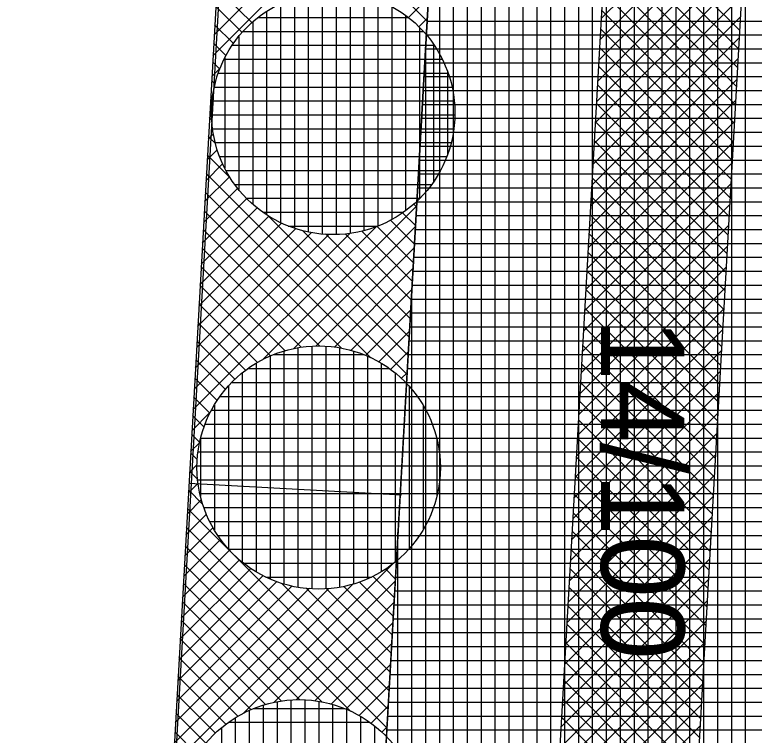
# Model space of a CAD drawing. Extents: x -565346 to -564154, y -1097386 to -1095620.
# Drawn here: x -564304.7 to -564294.07, y -1097238.87 to -1097228.5 of the extents above; entities that cross this region are included whole.
import ezdxf

# ---------------------------------------------------------------- set-up
doc = ezdxf.new("R2010")
doc.units = 0
for name, color, linetype in [('Vrstva 1', 7, 'Continuous'), ('Vrstva 40', 7, 'Continuous'), ('Vrstva 41', 7, 'Continuous'), ('Vrstva 42', 7, 'Continuous'), ('Vrstva 43', 7, 'Continuous'), ('Vrstva 44', 7, 'Continuous')]:
    doc.layers.add(name, color=color, linetype=linetype)

msp = doc.modelspace()

# ---------------------------------------------------------------- linework, layer by layer
at = {"layer": 'Vrstva 1'}
msp.add_line((-564307.09, -1097322.09), (-564296.5, -1097135.53), dxfattribs=at)
at = {"layer": 'Vrstva 41'}
msp.add_line((-564299.138, -1097235.414), (-564302.199, -1097235.242), dxfattribs=at)
msp.add_lwpolyline([(-564307.383, -1097332.191), (-564304.399, -1097332.838), (-564304.096, -1097322.37), (-564303.226, -1097307.04), (-564296.016, -1097180.02), (-564294.347, -1097150.646), (-564297.42, -1097150.37), (-564307.09, -1097322.09)], close=True, dxfattribs=at)
at = {"layer": 'Vrstva 42'}
for p, q in [((-564301.662, -1097225.698), (-564298.773, -1097228.587)), ((-564298.618, -1097225.855), (-564301.853, -1097229.09)), ((-564299.264, -1097226.218), (-564301.836, -1097228.79)), ((-564294.143, -1097226.43), (-564296.267, -1097228.554)), ((-564294.16, -1097226.73), (-564296.284, -1097228.854)), ((-564296.169, -1097226.831), (-564294.273, -1097228.727)), ((-564294.177, -1097227.03), (-564296.301, -1097229.154)), ((-564296.184, -1097227.099), (-564294.288, -1097228.995)), ((-564294.194, -1097227.33), (-564296.318, -1097229.454)), ((-564296.199, -1097227.367), (-564294.304, -1097229.263)), ((-564294.211, -1097227.63), (-564296.335, -1097229.754)), ((-564296.215, -1097227.634), (-564294.319, -1097229.53)), ((-564296.23, -1097227.902), (-564294.334, -1097229.798)), ((-564294.228, -1097227.93), (-564296.352, -1097230.054)), ((-564301.798, -1097228.107), (-564301.293, -1097228.612)), ((-564294.245, -1097228.23), (-564296.369, -1097230.354)), ((-564296.245, -1097228.17), (-564294.349, -1097230.065)), ((-564298.754, -1097228.254), (-564299.042, -1097228.542)), ((-564301.813, -1097228.375), (-564301.433, -1097228.754)), ((-564296.26, -1097228.437), (-564294.364, -1097230.333)), ((-564298.771, -1097228.554), (-564298.892, -1097228.675)), ((-564294.262, -1097228.529), (-564296.386, -1097230.653)), ((-564301.828, -1097228.643), (-564301.558, -1097228.913)), ((-564296.275, -1097228.705), (-564294.38, -1097230.601)), ((-564294.279, -1097228.829), (-564296.403, -1097230.953)), ((-564301.843, -1097228.911), (-564301.665, -1097229.088)), ((-564296.291, -1097228.973), (-564294.395, -1097230.868)), ((-564301.858, -1097229.179), (-564301.754, -1097229.283)), ((-564294.296, -1097229.129), (-564296.42, -1097231.253)), ((-564301.748, -1097229.268), (-564301.87, -1097229.39)), ((-564296.306, -1097229.24), (-564294.41, -1097231.136)), ((-564301.873, -1097229.446), (-564301.822, -1097229.498)), ((-564294.313, -1097229.429), (-564296.437, -1097231.553)), ((-564296.321, -1097229.508), (-564294.425, -1097231.404)), ((-564301.888, -1097229.714), (-564301.864, -1097229.738)), ((-564301.852, -1097229.655), (-564301.887, -1097229.69)), ((-564294.33, -1097229.729), (-564296.454, -1097231.853)), ((-564296.336, -1097229.776), (-564294.44, -1097231.671)), ((-564301.872, -1097229.957), (-564301.904, -1097229.989)), ((-564301.903, -1097229.982), (-564301.868, -1097230.017)), ((-564294.347, -1097230.029), (-564296.471, -1097232.153)), ((-564296.351, -1097230.043), (-564294.456, -1097231.939)), ((-564301.846, -1097230.214), (-564301.92, -1097230.289)), ((-564301.918, -1097230.25), (-564301.816, -1097230.352)), ((-564294.364, -1097230.329), (-564296.488, -1097232.453)), ((-564296.367, -1097230.311), (-564294.471, -1097232.207)), ((-564301.791, -1097230.443), (-564301.937, -1097230.589)), ((-564301.933, -1097230.517), (-564301.6, -1097230.851)), ((-564296.382, -1097230.578), (-564294.486, -1097232.474)), ((-564301.712, -1097230.647), (-564301.954, -1097230.888)), ((-564294.381, -1097230.628), (-564296.505, -1097232.753)), ((-564301.948, -1097230.785), (-564299.061, -1097233.672)), ((-564301.613, -1097230.83), (-564301.971, -1097231.188)), ((-564296.397, -1097230.846), (-564294.501, -1097232.742)), ((-564301.496, -1097230.996), (-564301.988, -1097231.488)), ((-564294.398, -1097230.928), (-564296.522, -1097233.052)), ((-564301.963, -1097231.053), (-564299.58, -1097233.436)), ((-564301.363, -1097231.146), (-564302.005, -1097231.788)), ((-564296.412, -1097231.114), (-564294.516, -1097233.01)), ((-564301.214, -1097231.28), (-564302.022, -1097232.087)), ((-564301.979, -1097231.321), (-564300.002, -1097233.297)), ((-564298.924, -1097231.252), (-564301.129, -1097233.457)), ((-564298.964, -1097231.223), (-564298.925, -1097231.263)), ((-564294.415, -1097231.228), (-564296.539, -1097233.352)), ((-564301.049, -1097231.398), (-564302.039, -1097232.387)), ((-564301.061, -1097231.39), (-564299.046, -1097233.404)), ((-564299.123, -1097231.348), (-564298.94, -1097231.531)), ((-564296.427, -1097231.381), (-564294.531, -1097233.277)), ((-564300.866, -1097231.498), (-564302.055, -1097232.687)), ((-564299.298, -1097231.455), (-564298.955, -1097231.798)), ((-564294.432, -1097231.528), (-564296.556, -1097233.652)), ((-564299.501, -1097231.547), (-564302.14, -1097234.185)), ((-564299.882, -1097231.645), (-564302.123, -1097233.886)), ((-564300.435, -1097231.632), (-564302.089, -1097233.286)), ((-564300.664, -1097231.578), (-564302.072, -1097232.987)), ((-564301.994, -1097231.588), (-564300.317, -1097233.265)), ((-564298.941, -1097231.552), (-564300.689, -1097233.301)), ((-564300.562, -1097231.606), (-564299.031, -1097233.137)), ((-564299.708, -1097231.612), (-564298.985, -1097232.334)), ((-564299.493, -1097231.544), (-564298.97, -1097232.066)), ((-564300.178, -1097231.658), (-564302.106, -1097233.586)), ((-564300.232, -1097231.653), (-564299.016, -1097232.869)), ((-564299.948, -1097231.654), (-564299.001, -1097232.601)), ((-564296.443, -1097231.649), (-564294.547, -1097233.545)), ((-564302.009, -1097231.856), (-564300.581, -1097233.284)), ((-564298.958, -1097231.852), (-564300.372, -1097233.266)), ((-564294.449, -1097231.828), (-564296.573, -1097233.952)), ((-564296.458, -1097231.917), (-564294.562, -1097233.813)), ((-564302.024, -1097232.124), (-564300.814, -1097233.334)), ((-564298.975, -1097232.152), (-564300.104, -1097233.281)), ((-564294.466, -1097232.128), (-564296.59, -1097234.252)), ((-564296.473, -1097232.184), (-564294.577, -1097234.08)), ((-564302.039, -1097232.392), (-564301.024, -1097233.407)), ((-564298.992, -1097232.452), (-564299.869, -1097233.329)), ((-564294.483, -1097232.428), (-564296.607, -1097234.552)), ((-564296.488, -1097232.452), (-564294.592, -1097234.348)), ((-564302.054, -1097232.659), (-564301.213, -1097233.501)), ((-564299.009, -1097232.752), (-564299.659, -1097233.401)), ((-564294.5, -1097232.728), (-564296.624, -1097234.852)), ((-564296.503, -1097232.72), (-564294.607, -1097234.616)), ((-564302.069, -1097232.927), (-564301.382, -1097233.614)), ((-564294.517, -1097233.027), (-564296.641, -1097235.151)), ((-564296.519, -1097232.987), (-564294.623, -1097234.883)), ((-564299.026, -1097233.052), (-564299.468, -1097233.493)), ((-564302.084, -1097233.195), (-564301.535, -1097233.744)), ((-564294.534, -1097233.327), (-564296.658, -1097235.451)), ((-564296.534, -1097233.255), (-564294.638, -1097235.151)), ((-564299.043, -1097233.352), (-564299.297, -1097233.605)), ((-564302.099, -1097233.463), (-564301.672, -1097233.89)), ((-564296.549, -1097233.523), (-564294.653, -1097235.419)), ((-564299.06, -1097233.651), (-564299.143, -1097233.734)), ((-564294.551, -1097233.627), (-564296.675, -1097235.751)), ((-564302.114, -1097233.731), (-564301.793, -1097234.052)), ((-564296.564, -1097233.79), (-564294.668, -1097235.686)), ((-564294.568, -1097233.927), (-564296.692, -1097236.051)), ((-564302.129, -1097233.998), (-564301.897, -1097234.231)), ((-564296.579, -1097234.058), (-564294.683, -1097235.954)), ((-564301.891, -1097234.219), (-564302.157, -1097234.485)), ((-564302.144, -1097234.266), (-564301.981, -1097234.429)), ((-564294.585, -1097234.227), (-564296.709, -1097236.351)), ((-564296.594, -1097234.326), (-564294.699, -1097236.221)), ((-564302.159, -1097234.534), (-564302.045, -1097234.648)), ((-564294.602, -1097234.527), (-564296.726, -1097236.651)), ((-564296.61, -1097234.593), (-564294.714, -1097236.489)), ((-564302.047, -1097234.659), (-564302.174, -1097234.785)), ((-564302.175, -1097234.802), (-564302.078, -1097234.898)), ((-564294.619, -1097234.827), (-564296.743, -1097236.951)), ((-564296.625, -1097234.861), (-564294.729, -1097236.757)), ((-564302.082, -1097234.976), (-564302.19, -1097235.085)), ((-564302.19, -1097235.069), (-564302.075, -1097235.184)), ((-564294.636, -1097235.126), (-564296.76, -1097237.25)), ((-564296.64, -1097235.129), (-564294.744, -1097237.024)), ((-564302.067, -1097235.244), (-564302.207, -1097235.384)), ((-564302.205, -1097235.337), (-564302.002, -1097235.54)), ((-564294.653, -1097235.426), (-564296.778, -1097237.55)), ((-564296.655, -1097235.396), (-564294.759, -1097237.292)), ((-564302.019, -1097235.479), (-564302.224, -1097235.684)), ((-564302.22, -1097235.605), (-564299.335, -1097238.49)), ((-564296.67, -1097235.664), (-564294.775, -1097237.56)), ((-564301.947, -1097235.689), (-564302.241, -1097235.984)), ((-564294.67, -1097235.726), (-564296.795, -1097237.85)), ((-564301.855, -1097235.88), (-564302.258, -1097236.283)), ((-564302.235, -1097235.873), (-564299.35, -1097238.757)), ((-564296.686, -1097235.931), (-564294.79, -1097237.827)), ((-564301.743, -1097236.051), (-564302.275, -1097236.583)), ((-564294.688, -1097236.026), (-564296.812, -1097238.15)), ((-564301.614, -1097236.205), (-564302.292, -1097236.883)), ((-564302.25, -1097236.14), (-564299.868, -1097238.522)), ((-564296.701, -1097236.199), (-564294.805, -1097238.095)), ((-564301.469, -1097236.343), (-564302.309, -1097237.183)), ((-564302.265, -1097236.408), (-564300.287, -1097238.386)), ((-564299.241, -1097236.378), (-564301.412, -1097238.549)), ((-564294.705, -1097236.326), (-564296.829, -1097238.45)), ((-564301.309, -1097236.465), (-564302.326, -1097237.482)), ((-564299.372, -1097236.473), (-564299.229, -1097236.616)), ((-564296.716, -1097236.467), (-564294.82, -1097238.363)), ((-564301.13, -1097236.57), (-564302.342, -1097237.782)), ((-564299.551, -1097236.577), (-564299.244, -1097236.884)), ((-564294.722, -1097236.626), (-564296.846, -1097238.75)), ((-564299.836, -1097236.69), (-564302.427, -1097239.281)), ((-564300.716, -1097236.721), (-564302.376, -1097238.382)), ((-564300.933, -1097236.656), (-564302.359, -1097238.082)), ((-564302.28, -1097236.676), (-564300.601, -1097238.355)), ((-564299.23, -1097236.65), (-564300.971, -1097238.391)), ((-564300.86, -1097236.682), (-564299.32, -1097238.222)), ((-564300.514, -1097236.745), (-564299.305, -1097237.954)), ((-564299.968, -1097236.725), (-564299.274, -1097237.419)), ((-564299.749, -1097236.661), (-564299.259, -1097237.151)), ((-564296.731, -1097236.734), (-564294.835, -1097238.63)), ((-564300.185, -1097236.756), (-564302.41, -1097238.981)), ((-564300.462, -1097236.751), (-564302.393, -1097238.681)), ((-564300.218, -1097236.758), (-564299.289, -1097237.687)), ((-564302.295, -1097236.944), (-564300.864, -1097238.374)), ((-564299.247, -1097236.95), (-564300.654, -1097238.356)), ((-564294.739, -1097236.926), (-564296.863, -1097239.05)), ((-564296.746, -1097237.002), (-564294.851, -1097238.898)), ((-564302.31, -1097237.211), (-564301.097, -1097238.424)), ((-564299.265, -1097237.25), (-564300.386, -1097238.371)), ((-564294.756, -1097237.225), (-564296.88, -1097239.35)), ((-564296.762, -1097237.27), (-564294.866, -1097239.166)), ((-564302.325, -1097237.479), (-564301.307, -1097238.498)), ((-564299.282, -1097237.55), (-564300.151, -1097238.419)), ((-564294.773, -1097237.525), (-564296.897, -1097239.649)), ((-564296.777, -1097237.537), (-564294.881, -1097239.433)), ((-564302.34, -1097237.747), (-564301.495, -1097238.592)), ((-564296.792, -1097237.805), (-564294.896, -1097239.701)), ((-564299.299, -1097237.849), (-564299.94, -1097238.491)), ((-564294.79, -1097237.825), (-564296.914, -1097239.949)), ((-564302.356, -1097238.015), (-564301.665, -1097238.706)), ((-564294.807, -1097238.125), (-564296.931, -1097240.249)), ((-564296.807, -1097238.073), (-564294.911, -1097239.969)), ((-564299.316, -1097238.149), (-564299.749, -1097238.583)), ((-564302.371, -1097238.282), (-564301.817, -1097238.836)), ((-564296.822, -1097238.34), (-564294.926, -1097240.236)), ((-564299.333, -1097238.449), (-564299.578, -1097238.694)), ((-564294.824, -1097238.425), (-564296.948, -1097240.549)), ((-564302.386, -1097238.55), (-564301.954, -1097238.982)), ((-564296.838, -1097238.608), (-564294.942, -1097240.504)), ((-564299.35, -1097238.749), (-564299.424, -1097238.823)), ((-564294.841, -1097238.725), (-564296.965, -1097240.849)), ((-564302.401, -1097238.818), (-564302.075, -1097239.144))]:
    msp.add_line(p, q, dxfattribs=at)
msp.add_lwpolyline([(-564300.922, -1097310.531), (-564298.925, -1097310.644), (-564291.523, -1097180.275), (-564289.854, -1097150.901), (-564291.851, -1097150.788), (-564293.52, -1097180.162), (-564300.73, -1097307.182)], close=True, dxfattribs=at)
at = {"layer": 'Vrstva 43'}
for p, q in [((-564294.19, -1097271.373), (-564294.19, -1097138.944)), ((-564294.39, -1097274.897), (-564294.39, -1097151.403)), ((-564294.59, -1097278.421), (-564294.59, -1097154.926)), ((-564294.79, -1097281.945), (-564294.79, -1097158.449)), ((-564294.99, -1097285.469), (-564294.99, -1097161.972)), ((-564295.19, -1097288.993), (-564295.19, -1097165.495)), ((-564295.39, -1097292.517), (-564295.39, -1097169.017)), ((-564295.59, -1097296.041), (-564295.59, -1097172.54)), ((-564295.79, -1097299.565), (-564295.79, -1097176.063)), ((-564295.99, -1097303.088), (-564295.99, -1097179.586)), ((-564296.19, -1097306.612), (-564296.19, -1097183.108)), ((-564296.39, -1097310.136), (-564296.39, -1097186.631)), ((-564296.59, -1097313.66), (-564296.59, -1097190.154)), ((-564296.79, -1097317.184), (-564296.79, -1097193.677)), ((-564296.99, -1097320.708), (-564296.99, -1097197.2)), ((-564297.19, -1097322.532), (-564297.19, -1097200.722)), ((-564297.39, -1097322.908), (-564297.39, -1097204.245)), ((-564297.59, -1097323.285), (-564297.59, -1097207.768)), ((-564297.79, -1097323.661), (-564297.79, -1097211.291)), ((-564297.99, -1097324.037), (-564297.99, -1097214.814)), ((-564298.19, -1097324.413), (-564298.19, -1097218.336)), ((-564298.39, -1097324.789), (-564298.39, -1097221.859)), ((-564298.59, -1097325.166), (-564298.59, -1097225.382)), ((-564298.772, -1097228.59), (-564291.762, -1097228.59)), ((-564298.783, -1097228.79), (-564291.773, -1097228.79)), ((-564298.79, -1097325.542), (-564298.79, -1097228.905)), ((-564298.795, -1097228.99), (-564291.784, -1097228.99)), ((-564298.806, -1097229.19), (-564291.796, -1097229.19)), ((-564298.818, -1097229.39), (-564291.807, -1097229.39)), ((-564298.829, -1097229.59), (-564291.818, -1097229.59)), ((-564298.84, -1097229.79), (-564291.83, -1097229.79)), ((-564298.852, -1097229.99), (-564291.841, -1097229.99)), ((-564298.863, -1097230.19), (-564291.852, -1097230.19)), ((-564298.874, -1097230.39), (-564291.864, -1097230.39)), ((-564298.886, -1097230.59), (-564291.875, -1097230.59)), ((-564298.897, -1097230.79), (-564291.886, -1097230.79)), ((-564298.908, -1097230.99), (-564291.898, -1097230.99)), ((-564298.92, -1097231.19), (-564291.909, -1097231.19)), ((-564298.931, -1097231.39), (-564291.921, -1097231.39)), ((-564298.942, -1097231.59), (-564291.932, -1097231.59)), ((-564298.954, -1097231.79), (-564291.943, -1097231.79)), ((-564298.965, -1097231.99), (-564291.955, -1097231.99)), ((-564298.977, -1097232.19), (-564291.966, -1097232.19)), ((-564298.99, -1097325.918), (-564298.99, -1097232.427)), ((-564298.988, -1097232.39), (-564291.977, -1097232.39)), ((-564298.999, -1097232.59), (-564291.989, -1097232.59)), ((-564299.011, -1097232.79), (-564292, -1097232.79)), ((-564299.022, -1097232.99), (-564292.011, -1097232.99)), ((-564299.033, -1097233.19), (-564292.023, -1097233.19)), ((-564299.045, -1097233.39), (-564292.034, -1097233.39)), ((-564299.056, -1097233.59), (-564292.045, -1097233.59)), ((-564299.067, -1097233.79), (-564292.057, -1097233.79)), ((-564299.079, -1097233.99), (-564292.068, -1097233.99)), ((-564299.09, -1097234.19), (-564292.079, -1097234.19)), ((-564299.101, -1097234.39), (-564292.091, -1097234.39)), ((-564299.113, -1097234.59), (-564292.102, -1097234.59)), ((-564299.124, -1097234.79), (-564292.114, -1097234.79)), ((-564299.135, -1097234.99), (-564292.125, -1097234.99)), ((-564299.147, -1097235.19), (-564292.136, -1097235.19)), ((-564299.158, -1097235.39), (-564292.148, -1097235.39)), ((-564299.17, -1097235.59), (-564292.159, -1097235.59)), ((-564299.181, -1097235.79), (-564292.17, -1097235.79)), ((-564299.192, -1097235.99), (-564292.182, -1097235.99)), ((-564299.19, -1097326.294), (-564299.19, -1097235.95)), ((-564299.204, -1097236.19), (-564292.193, -1097236.19)), ((-564299.215, -1097236.39), (-564292.204, -1097236.39)), ((-564299.226, -1097236.59), (-564292.216, -1097236.59)), ((-564299.238, -1097236.79), (-564292.227, -1097236.79)), ((-564299.249, -1097236.99), (-564292.238, -1097236.99)), ((-564299.26, -1097237.19), (-564292.25, -1097237.19)), ((-564299.272, -1097237.39), (-564292.261, -1097237.39)), ((-564299.283, -1097237.59), (-564292.272, -1097237.59)), ((-564299.294, -1097237.79), (-564292.284, -1097237.79)), ((-564299.306, -1097237.99), (-564292.295, -1097237.99)), ((-564299.317, -1097238.19), (-564292.307, -1097238.19)), ((-564299.329, -1097238.39), (-564292.318, -1097238.39)), ((-564299.34, -1097238.59), (-564292.329, -1097238.59)), ((-564299.351, -1097238.79), (-564292.341, -1097238.79))]:
    msp.add_line(p, q, dxfattribs=at)
msp.add_lwpolyline([(-564283.37, -1096906.18), (-564284.87, -1096930.83), (-564282.373, -1096930.972), (-564294.286, -1097140.634), (-564296.782, -1097140.492), (-564297.42, -1097150.37), (-564294.347, -1097150.646), (-564303.226, -1097307.04), (-564304.096, -1097322.37), (-564304.399, -1097332.838), (-564302.848, -1097333.175), (-564297.082, -1097322.329), (-564293.197, -1097253.877), (-564289.027, -1097180.417), (-564287.358, -1097151.043), (-564285.364, -1097151.156), (-564284.798, -1097141.172), (-564286.791, -1097141.059), (-564274.888, -1096931.397), (-564272.899, -1096931.51), (-564271.475, -1096906.55)], dxfattribs=at)
at = {"layer": 'Vrstva 44'}
for p, q in [((-564300.48, -1097228.203), (-564300.48, -1097231.626)), ((-564300.28, -1097228.172), (-564300.28, -1097231.655)), ((-564300.08, -1097228.165), (-564300.08, -1097231.662)), ((-564299.88, -1097228.183), (-564299.88, -1097231.646)), ((-564299.68, -1097228.223), (-564299.68, -1097231.607)), ((-564300.88, -1097228.338), (-564300.88, -1097231.489)), ((-564300.68, -1097228.258), (-564300.68, -1097231.571)), ((-564299.48, -1097228.287), (-564299.48, -1097231.541)), ((-564301.08, -1097228.451), (-564301.08, -1097231.378)), ((-564299.28, -1097228.381), (-564299.28, -1097231.446)), ((-564301.204, -1097228.54), (-564299.04, -1097228.54)), ((-564299.08, -1097228.51), (-564299.08, -1097231.32)), ((-564301.28, -1097228.605), (-564301.28, -1097231.223)), ((-564301.418, -1097228.74), (-564298.827, -1097228.74)), ((-564298.88, -1097228.682), (-564298.88, -1097231.145)), ((-564301.48, -1097228.814), (-564301.48, -1097231.015)), ((-564301.573, -1097228.94), (-564298.669, -1097228.94)), ((-564298.68, -1097228.922), (-564298.68, -1097230.903)), ((-564301.69, -1097229.14), (-564298.554, -1097229.14)), ((-564301.68, -1097229.122), (-564301.68, -1097230.706)), ((-564301.774, -1097229.34), (-564298.47, -1097229.34)), ((-564298.48, -1097229.313), (-564298.48, -1097230.52)), ((-564301.829, -1097229.54), (-564298.412, -1097229.54)), ((-564301.861, -1097229.74), (-564298.382, -1097229.74)), ((-564301.87, -1097229.94), (-564298.374, -1097229.94)), ((-564301.856, -1097230.14), (-564298.388, -1097230.14)), ((-564301.818, -1097230.34), (-564298.425, -1097230.34)), ((-564301.754, -1097230.54), (-564298.488, -1097230.54)), ((-564301.663, -1097230.74), (-564298.581, -1097230.74)), ((-564301.538, -1097230.94), (-564298.705, -1097230.94)), ((-564301.368, -1097231.14), (-564298.875, -1097231.14)), ((-564301.133, -1097231.34), (-564299.11, -1097231.34)), ((-564300.768, -1097231.54), (-564299.478, -1097231.54)), ((-564300.83, -1097233.338), (-564300.83, -1097236.691)), ((-564300.63, -1097233.29), (-564300.63, -1097236.736)), ((-564300.43, -1097233.269), (-564300.43, -1097236.76)), ((-564300.23, -1097233.269), (-564300.23, -1097236.761)), ((-564300.03, -1097233.292), (-564300.03, -1097236.737)), ((-564299.83, -1097233.338), (-564299.83, -1097236.689)), ((-564301.03, -1097233.412), (-564301.03, -1097236.617)), ((-564300.981, -1097233.39), (-564299.683, -1097233.39)), ((-564299.63, -1097233.412), (-564299.63, -1097236.615)), ((-564301.23, -1097233.514), (-564301.23, -1097236.514)), ((-564299.43, -1097233.517), (-564299.43, -1097236.514)), ((-564301.43, -1097233.654), (-564301.43, -1097236.375)), ((-564301.345, -1097233.59), (-564299.317, -1097233.59)), ((-564299.23, -1097233.655), (-564299.23, -1097236.372)), ((-564301.63, -1097233.842), (-564301.63, -1097236.185)), ((-564301.579, -1097233.79), (-564299.082, -1097233.79)), ((-564299.03, -1097233.847), (-564299.03, -1097236.183)), ((-564301.75, -1097233.99), (-564298.914, -1097233.99)), ((-564301.873, -1097234.19), (-564298.789, -1097234.19)), ((-564301.83, -1097234.112), (-564301.83, -1097235.915)), ((-564298.83, -1097234.119), (-564298.83, -1097235.912)), ((-564301.965, -1097234.39), (-564298.699, -1097234.39)), ((-564302.03, -1097234.594), (-564302.03, -1097235.432)), ((-564302.029, -1097234.59), (-564298.635, -1097234.59)), ((-564298.63, -1097234.609), (-564298.63, -1097235.416)), ((-564302.066, -1097234.79), (-564298.596, -1097234.79)), ((-564302.079, -1097234.99), (-564298.583, -1097234.99)), ((-564302.071, -1097235.19), (-564298.592, -1097235.19)), ((-564302.039, -1097235.39), (-564298.624, -1097235.39)), ((-564301.983, -1097235.59), (-564298.68, -1097235.59)), ((-564301.898, -1097235.79), (-564298.763, -1097235.79)), ((-564301.782, -1097235.99), (-564298.881, -1097235.99)), ((-564301.625, -1097236.19), (-564299.035, -1097236.19)), ((-564301.412, -1097236.39), (-564299.252, -1097236.39)), ((-564301.089, -1097236.59), (-564299.57, -1097236.59)), ((-564301.13, -1097238.434), (-564301.13, -1097241.775)), ((-564300.93, -1097238.384), (-564300.93, -1097241.823)), ((-564300.73, -1097238.359), (-564300.73, -1097241.848)), ((-564300.53, -1097238.358), (-564300.53, -1097241.851)), ((-564300.33, -1097238.379), (-564300.33, -1097241.831)), ((-564300.13, -1097238.423), (-564300.13, -1097241.785)), ((-564301.33, -1097238.51), (-564301.33, -1097241.698)), ((-564301.262, -1097238.48), (-564299.964, -1097238.48)), ((-564299.93, -1097238.493), (-564299.93, -1097241.713)), ((-564301.53, -1097238.615), (-564301.53, -1097241.593)), ((-564299.73, -1097238.595), (-564299.73, -1097241.614)), ((-564301.73, -1097238.76), (-564301.73, -1097241.449)), ((-564301.626, -1097238.68), (-564299.598, -1097238.68)), ((-564299.53, -1097238.73), (-564299.53, -1097241.477))]:
    msp.add_line(p, q, dxfattribs=at)
for centre in [(-564300.122, -1097229.914), (-564300.331, -1097235.014), (-564300.612, -1097240.104)]:
    msp.add_circle(centre, 1.75, dxfattribs=at)

# ---------------------------------------------------------------- texts
at = {"layer": 'Vrstva 40'}
msp.add_text('14/100', height=1.2, rotation=270, dxfattribs=at).set_placement((-564296.27, -1097232.87))

doc.saveas('drawing.dxf')
